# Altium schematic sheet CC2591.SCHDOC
size 999 x 999 mm
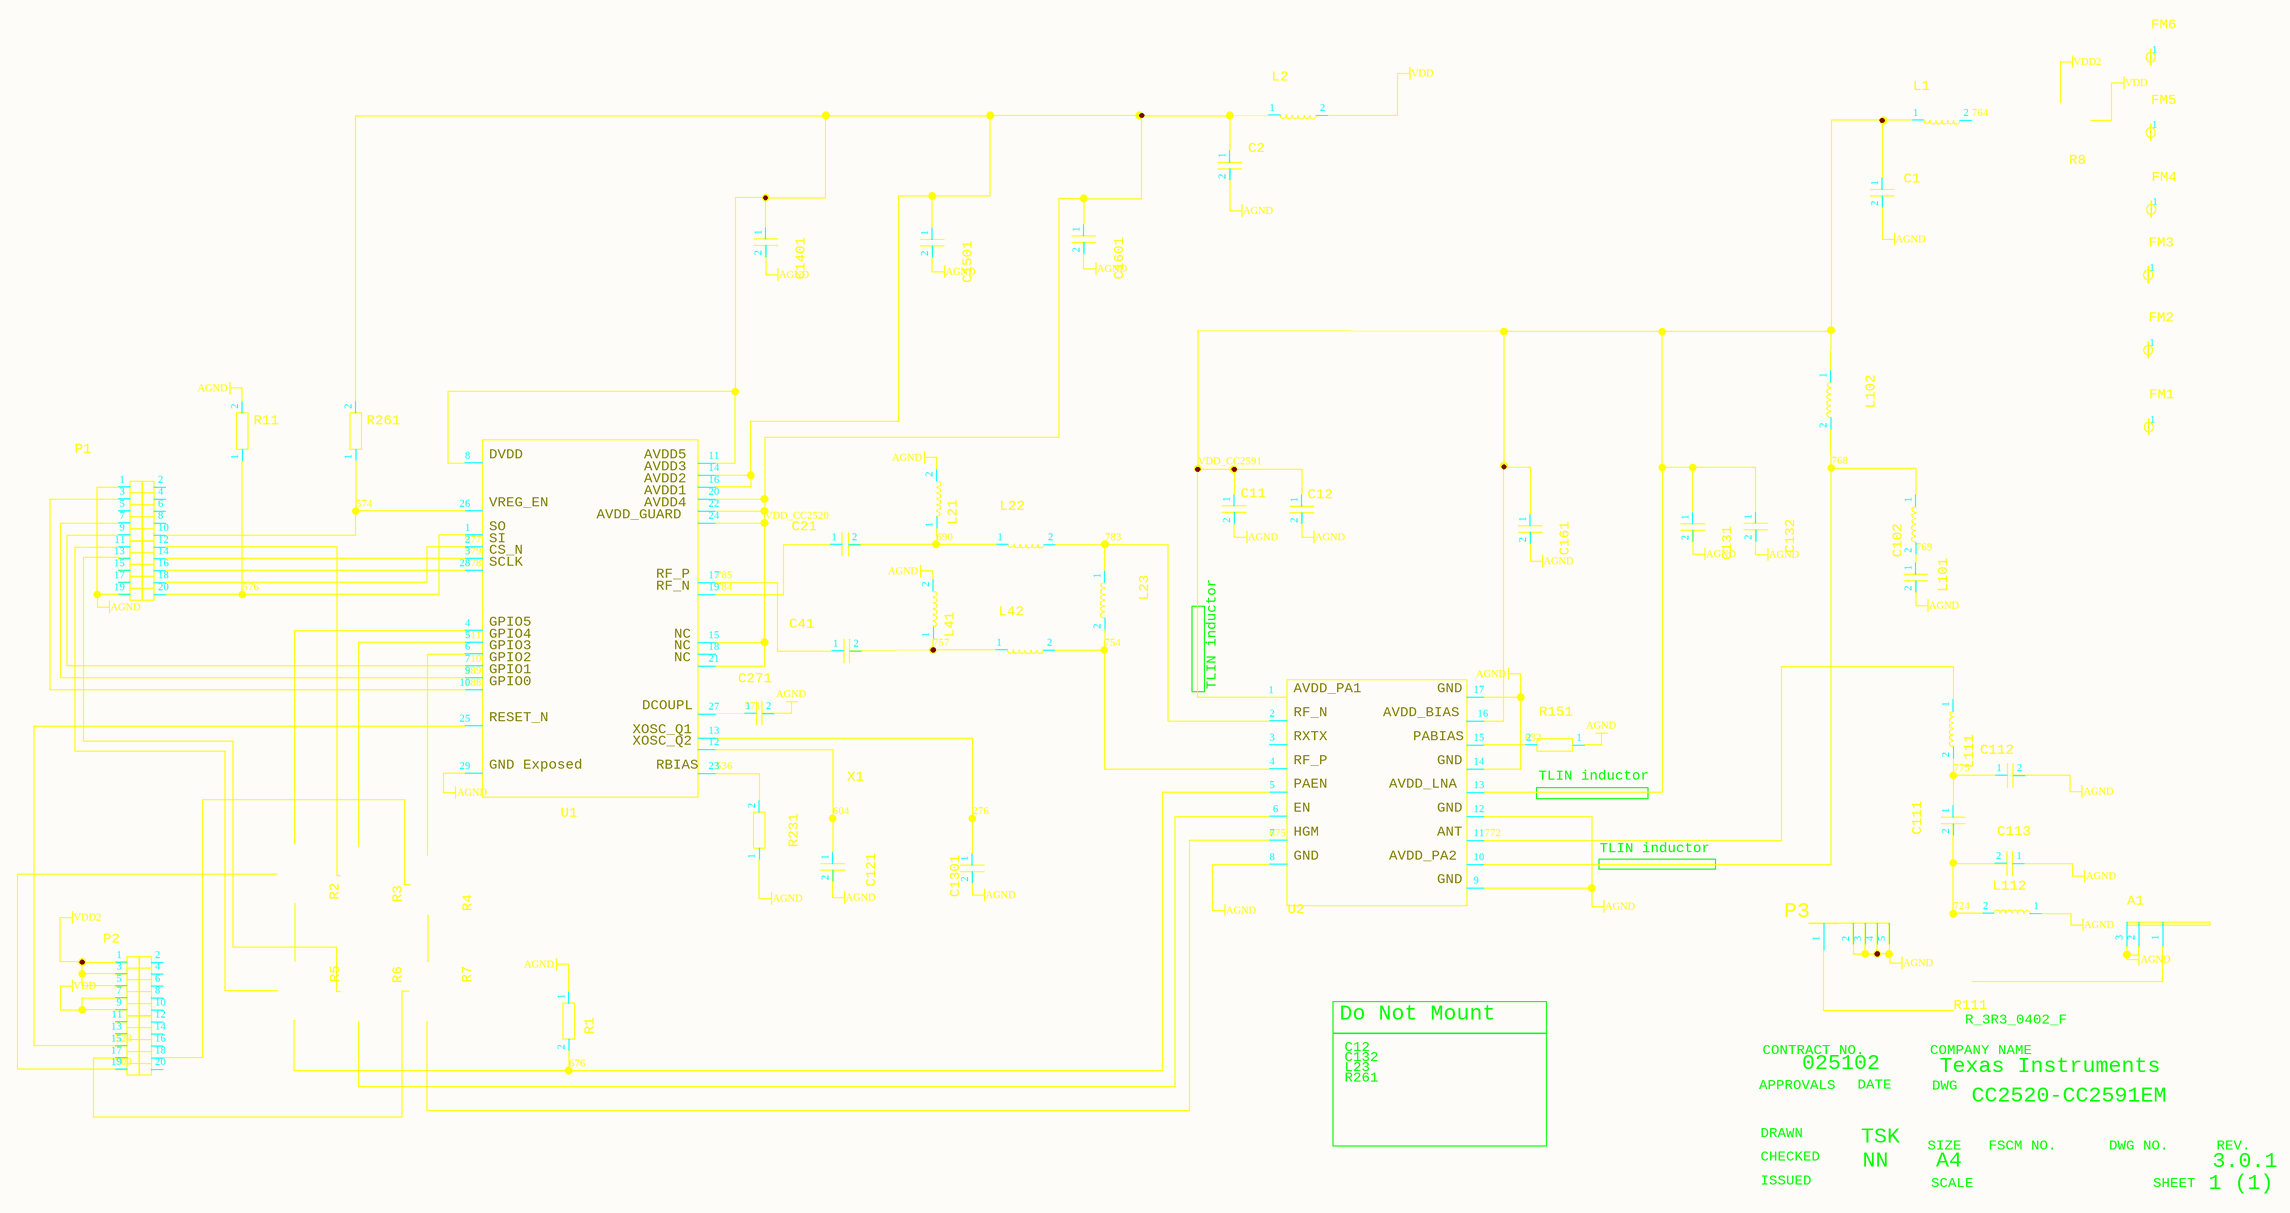
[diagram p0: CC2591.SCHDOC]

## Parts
A1  *  (value not drawn)
C1  *  (value not drawn)
C2  *  (value not drawn)
C11  *  (value not drawn)
C12  *  (value not drawn)
C21  *  (value not drawn)
C41  *  (value not drawn)
C102  *  (value not drawn)
C111  *  (value not drawn)
C112  *  (value not drawn)
C113  *  (value not drawn)
C121  *  (value not drawn)
C131  *  (value not drawn)
C132  *  (value not drawn)
C161  *  (value not drawn)
C271  *  (value not drawn)
C1301  *  (value not drawn)
C1401  *  (value not drawn)
C1501  *  (value not drawn)
C1601  *  (value not drawn)
FM1  *  (value not drawn)
FM2  *  (value not drawn)
FM3  *  (value not drawn)
FM4  *  (value not drawn)
FM5  *  (value not drawn)
FM6  *  (value not drawn)
L1  *  (value not drawn)
L2  *  (value not drawn)
L21  *  (value not drawn)
L22  *  (value not drawn)
L23  *  (value not drawn)
L41  *  (value not drawn)
L42  *  (value not drawn)
L101  *  (value not drawn)
L102  *  (value not drawn)
L111  *  (value not drawn)
L112  *  (value not drawn)
P1  *  (value not drawn)
P2  *  (value not drawn)
P3  *  (value not drawn)
R1  *  (value not drawn)
R2  *  (value not drawn)
R3  *  (value not drawn)
R4  *  (value not drawn)
R5  *  (value not drawn)
R6  *  (value not drawn)
R7  *  (value not drawn)
R8  *  (value not drawn)
R11  *  (value not drawn)
R111  *  (value not drawn)
R151  *  (value not drawn)
R231  *  (value not drawn)
R261  *  (value not drawn)
U1  *  (value not drawn)
U2  *  (value not drawn)
X1  *  (value not drawn)

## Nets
AGND: A1.2 A1.3 C1.2 C2.2 C11.2 C12.2 C112.2 C113.1 C121.2 C131.2 C132.2 C161.2 C271.2 C1301.2 C1401.2 C1501.2 C1601.2 L21.2 L41.2 L101.2 L112.1 P1.1 P1.19 P3.2 P3.3 P3.4 P3.5 R1.1 R11.2 R151.1 R231.1 U1.29 U2.8 U2.9 U2.12 U2.14 U2.17
VDD: L2.2 P2.7 P2.9
VDD2: P2.1 P2.3 P2.5
276: C1301.1 U1.13
528: P2.15 U1.25
536: R231.2 U1.23
571: C271.1 U1.27
574: P1.10 R261.1 U1.26
576: P1.20 R11.1 U1.1
577: P1.18 U1.2
578: P1.16 U1.28
579: P1.14 U1.3
588: P1.3 U1.10
589: P1.7 U1.9
604: C121.1 U1.12
632: R151.2 U2.15
675: U2.7
676: R1.2 U2.5
690: C21.2 L21.1 L22.1
709: P2.19
710: P1.9 U1.7
711: U1.5
724: C111.2 C113.2 L112.2
754: L23.2 L42.2 U2.4
757: C41.2 L41.1 L42.1
764: L1.2
768: C102.1 L102.2 U2.10
769: C102.2 L101.1
772: L111.1 U2.11
775: C111.1 C112.1 L111.2
783: L22.2 L23.1 U2.2
784: C21.1 U1.19
785: C41.1 U1.17
VDD_CC2520: C2.1 C1401.1 C1501.1 C1601.1 L2.1 R261.2 U1.8 U1.11 U1.14 U1.15 U1.16 U1.20 U1.21 U1.22 U1.24
VDD_CC2591: C1.1 C11.1 C12.1 C131.1 C132.1 C161.1 L1.1 L102.1 U2.1 U2.13 U2.16

Not connected (* = marked no-connect by the designer): A1 1; FM1 1; FM2 1; FM3 1; FM4 1; FM5 1; FM6 1; P1 2 4 5 6 8 11 12 13 15 17; P2 2 4 6 8 10 11 12 13 14 16 17 18 20; P3 1; U1 4 6 18; U2 3 6

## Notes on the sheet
- (near U2) TLIN inductor
- (near R151) TLIN inductor
- TLIN inductor
- Do Not Mount
- (near R111) R_3R3_0402_F
- R261
- L23
- C132
- C12
- APPROVALS
- CONTRACT NO.
- 025102
- DATE
- (near R111) COMPANY NAME
- DWG
- (near R111) Texas Instruments
- DRAWN
- CHECKED
- TSK
- SIZE
- CC2520-CC2591EM
- FSCM NO.
- DWG NO.
- REV.
- ISSUED
- NN
- SCALE
- A4
- SHEET
- 1 (1)
- 3.0.1

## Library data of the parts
A1 = Antenna_IIFA_cc2420: Antenna single ended IIFA, CC2420
C1 C2 = C_2U2_0402_X5R_M_4VDC: Capasitor 0402, GRM155R60G225ME15J; pick_and_place: P
C11 C131 C161 = C_1N_0402_NP0_J_50: Capacitor 0402; pick_and_place: P
C12 C132 = C_0402: Capacitor 0402, general; pick_and_place: P
C21 = C_3P0_0402_NP0_C_50: Capacitor 0603; pick_and_place: P
C41 = C_3P9_0402_NP0_C_50: Capacitor 0402; pick_and_place: P
C102 = L_1N1_0402_S: Inductor, 1n1, 0402, LQG15HS1N1S02D; pick_and_place: P
C111 = C_6P8_0402_NP0_C_50: Capacitor 0402; pick_and_place: P
C112 = C_1P0_0402_NP0_B_50: Capacitor, 1p, 0402, NP0, +/-0.1pF 50V; pick_and_place: P
C113 = C_2P7_0402_NP0_C_50: Capacitor 0402; pick_and_place: P
C121 C1301 = C_27P_0402_NP0_J_50: Capacitor 0402; pick_and_place: P
C271 C1401 C1501 C1601 = C_100N_0402_X5R_K_10: Capacitor 0402; pick_and_place: P
FM1-FM6 = FIDUCIAL_MARK_1MM: Fiducial mark, 1mm metal diameter; pick_and_place: P
L1 L2 = L_BEAD_102_0402: EMI filter bead; pick_and_place: P
L21 L41 L42 L112 = L_1N0_0402_S: Inductor 0402; pick_and_place: P
L22 = L_2N0_0402_S: Inductor 0402; pick_and_place: P
L23 = L_0402: Inductor 0402, general; pick_and_place: P
L101 = C_15P_0402_NP0_J_50: Capacitor, 0402; pick_and_place: P
L102 = L_5N1_0402_J: Inductor 0402; pick_and_place: P
L111 = L_1N5_0402_B_LQW: Inductor, 1n5, 0402, Wire-wound type, +/-0.1 nH; pick_and_place: P
P1 P2 = SMD_SOCKET_2X10: SMD pinrow socket, .050 spacing, SFM-110-02-SM-D-A-K-TR; pick_and_place: P; link Datasheet: G:\06_TEKNISK\064_Datasheets\Samtec\SFM_SM.pdf
P3 = SMA_SMD: Surface-mount SMA, straight; pick_and_place: P
R1 = R_330K_0402_F: Resistor 0402; pick_and_place: P
R2-R8 = R_0_0402_3PORT_1-2: 0402 3-port footprint, default connection 1-2; pick_and_place: P
R11 = R_1M0_0402_F: Resistor 0402; pick_and_place: P
R111 = R_0_0402_3PORT_2-3: 0402 3-port footprint, default connection 2-3; pick_and_place: P
R151 = R_4K3_0402_G: Resistor 0402; pick_and_place: P
R231 = R_56K_0402_F: Resistor 0402; pick_and_place: P
R261 = R_0402: Resistor 0402, general; pick_and_place: P
U1 = CC2520: Single-chip transceiver; pick_and_place: P
U2 = CC2591_DATASHEET: CC2591 w/ datasheet footprint; pick_and_place: P
X1 = X_32.000/10/15/30/16: Crystal, ceramic SMD 3.2x2.5mm; pick_and_place: P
